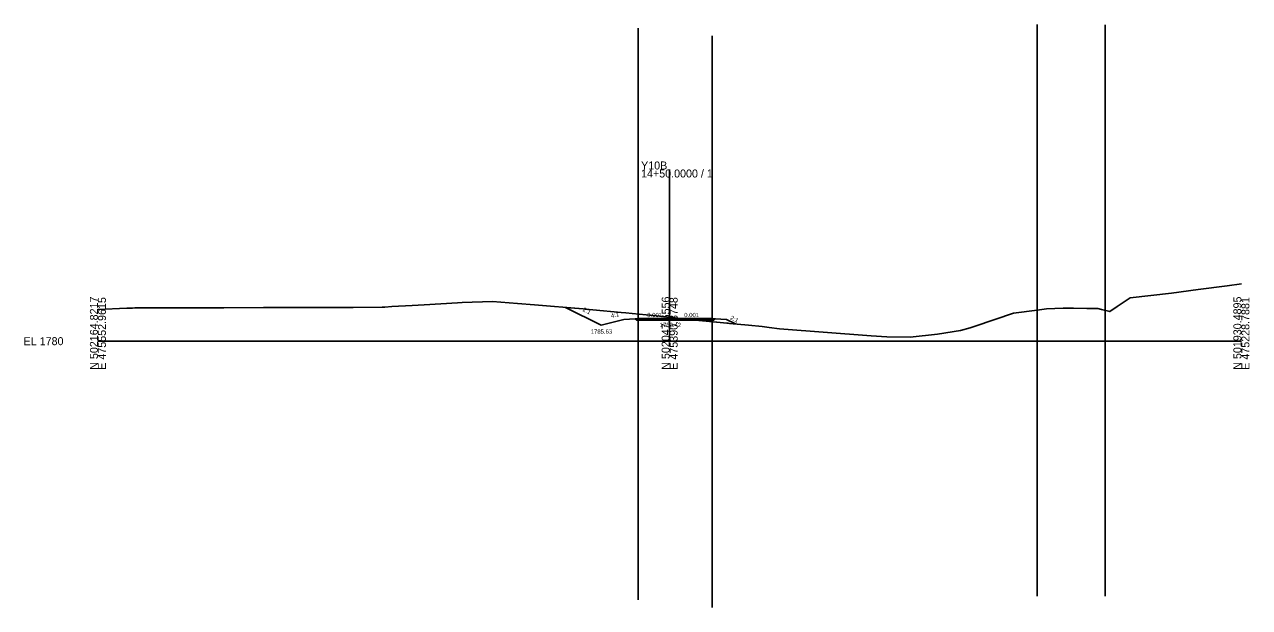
# Model space of a CAD drawing. Extents: x -26 to 1803, y -10 to 9558.
# Drawn here: x -25.7 to 402.8, y 4406.8 to 4610.8 of the extents above; entities that cross this region are included whole.
import ezdxf

# ---------------------------------------------------------------- set-up
doc = ezdxf.new("R2010")
doc.units = 0
for name, color, linetype in [('Exist Cross Section Cell', 7, 'Continuous'), ('Exist XS Center Line Elevation Label', 7, 'Continuous'), ('Exist XS Ground Line', 7, 'Continuous'), ('Prop XS Ditch Slope Text', 7, 'Continuous'), ('Prop XS Ditch Standard Text', 7, 'Continuous'), ('Prop XS Dump Level', 7, 'Continuous'), ('Prop XS Earthwork Shape', 7, 'Continuous'), ('Prop XS EOT Tick Mark', 7, 'Continuous'), ('Prop XS Finish Grade', 7, 'Continuous'), ('Prop XS Finish Grade Earthwork', 7, 'Continuous'), ('Prop XS Finish Grade Pavement', 7, 'Continuous'), ('Prop XS Hydro Typical Ditch Data', 7, 'Continuous'), ('Prop XS Pvmt Edge Slope', 7, 'Continuous'), ('Prop XS SE Text', 7, 'Continuous'), ('Prop XS Shoulder Borrow Shape', 7, 'Continuous'), ('Prop XS Side Slope Text', 7, 'Continuous'), ('Prop XS Subgrade Earthwork', 7, 'Continuous'), ('Scratch_Level_2', 7, 'Continuous')]:
    doc.layers.add(name, color=color, linetype=linetype)

msp = doc.modelspace()

# ---------------------------------------------------------------- linework, layer by layer
at = {"layer": 'Exist Cross Section Cell'}
for p, q in [((200, 4500), (200, 4560.08)), ((0, 4500), (200, 4500)), ((200, 4500), (400, 4500))]:
    msp.add_line(p, q, dxfattribs=at)
at = {"layer": 'Exist XS Ground Line'}
msp.add_lwpolyline([(0, 4511.14), (10.11, 4511.51), (12.07, 4511.59), (12.96, 4511.64), (13.97, 4511.69), (28.3, 4511.71), (30.98, 4511.72), (44.04, 4511.7), (57.97, 4511.76), (60.73, 4511.82), (75.68, 4511.8), (76.03, 4511.8), (83.09, 4511.82), (89.26, 4511.83), (99.44, 4511.91), (100.32, 4511.92), (102.83, 4512.12), (109.93, 4512.46), (114.09, 4512.75), (125.78, 4513.41), (127.45, 4513.54), (138.01, 4513.83), (146.74, 4513.17), (152.68, 4512.7), (158.34, 4512.29), (169.75, 4511.29), (170.68, 4511.19), (173.11, 4510.96), (183.03, 4510.05), (184.62, 4509.9), (186.83, 4509.7), (191.78, 4509.24), (195.37, 4508.89), (198.95, 4508.55), (200, 4508.42), (203.9, 4507.94), (207.71, 4507.5), (217.64, 4506.53), (220.05, 4506.29), (220.44, 4506.26), (220.97, 4506.21), (227.6, 4505.61), (232.39, 4505.1), (234.76, 4504.82), (238.43, 4504.33), (270.49, 4501.88), (275.97, 4501.51), (284.12, 4501.39), (293.66, 4502.51), (301.73, 4503.78), (305.18, 4504.67), (306.87, 4505.24), (320.31, 4509.82), (328.54, 4510.82), (331.86, 4511.36), (337.61, 4511.51), (341.27, 4511.59), (345.96, 4511.48), (349.82, 4511.41), (351.1, 4511.09), (353.98, 4510.33), (356.49, 4512.14), (361.08, 4515.14), (375.53, 4516.79), (384.91, 4518.14), (394.98, 4519.32), (400, 4520.03)], dxfattribs=at)
at = {"layer": 'Prop XS Dump Level'}
for p, q in [((189, 4507.93), (200, 4507.92)), ((200, 4507.92), (214.9, 4507.9))]:
    msp.add_line(p, q, dxfattribs=at)
at = {"layer": 'Prop XS Earthwork Shape'}
for points in [[(176, 4505.63), (163.61, 4511.83), (169.75, 4511.29), (170.68, 4511.19), (173.11, 4510.96), (183.03, 4510.05), (184.62, 4509.9), (186.83, 4509.7), (191.78, 4509.24), (195.37, 4508.89), (198.95, 4508.55), (200, 4508.42), (203.9, 4507.94), (207.71, 4507.5), (209.11, 4507.37), (200, 4507.37), (189, 4507.39), (188.46, 4507.39), (187.98, 4507.87), (184, 4507.63)], [(223.06, 4506.02), (219.9, 4507.6), (215.92, 4507.84), (215.44, 4507.36), (214.9, 4507.36), (209.11, 4507.37), (217.64, 4506.53), (220.05, 4506.29), (220.44, 4506.26), (220.97, 4506.21)]]:
    msp.add_lwpolyline(points, close=True, dxfattribs=at)
at = {"layer": 'Prop XS EOT Tick Mark'}
for p, q in [((189, 4507.93), (189, 4508.93)), ((214.9, 4507.9), (214.9, 4508.9))]:
    msp.add_line(p, q, dxfattribs=at)
at = {"layer": 'Prop XS Finish Grade'}
for p, q in [((189, 4507.93), (187.98, 4507.87)), ((214.9, 4507.9), (215.92, 4507.84))]:
    msp.add_line(p, q, dxfattribs=at)
at = {"layer": 'Prop XS Finish Grade Earthwork'}
for p, q in [((176, 4505.63), (163.61, 4511.83)), ((184, 4507.63), (176, 4505.63)), ((187.98, 4507.87), (184, 4507.63)), ((215.92, 4507.84), (219.9, 4507.6)), ((223.06, 4506.02), (219.9, 4507.6))]:
    msp.add_line(p, q, dxfattribs=at)
at = {"layer": 'Prop XS Finish Grade Pavement'}
for p, q in [((189, 4507.93), (200, 4507.92)), ((200, 4507.92), (214.9, 4507.9))]:
    msp.add_line(p, q, dxfattribs=at)
at = {"layer": 'Prop XS Hydro Typical Ditch Data'}
for p, q in [((176, 4505.63), (163.61, 4511.83)), ((184, 4507.63), (176, 4505.63)), ((223.06, 4506.02), (219.9, 4507.6))]:
    msp.add_line(p, q, dxfattribs=at)
at = {"layer": 'Prop XS Pvmt Edge Slope'}
for p, q in [((189, 4507.93), (188.46, 4507.39)), ((214.9, 4507.9), (215.44, 4507.36))]:
    msp.add_line(p, q, dxfattribs=at)
at = {"layer": 'Prop XS Shoulder Borrow Shape'}
for points in [[(189, 4507.93), (187.98, 4507.87), (188.46, 4507.39)], [(214.9, 4507.9), (215.44, 4507.36), (215.92, 4507.84)]]:
    msp.add_lwpolyline(points, close=True, dxfattribs=at)
at = {"layer": 'Prop XS Subgrade Earthwork'}
for p, q in [((188.46, 4507.39), (187.98, 4507.87)), ((189, 4507.39), (188.46, 4507.39)), ((200, 4507.37), (189, 4507.39)), ((214.9, 4507.36), (200, 4507.37)), ((214.9, 4507.36), (215.44, 4507.36)), ((215.44, 4507.36), (215.92, 4507.84))]:
    msp.add_line(p, q, dxfattribs=at)
at = {"layer": 'Scratch_Level_2'}
for p, q in [((189, 4609.5), (189, 4409.5)), ((214.9, 4606.8), (214.9, 4406.8)), ((328.54, 4610.82), (328.54, 4410.82)), ((352.38, 4610.75), (352.38, 4410.75))]:
    msp.add_line(p, q, dxfattribs=at)

# ---------------------------------------------------------------- texts
at = {"layer": 'Exist Cross Section Cell'}
for s, p in [('Y10B', (190, 4560.08)), ('14+50.0000 / 1', (190, 4557.28)), ('EL 1780', (-26, 4498.6))]:
    msp.add_text(s, height=2.8, dxfattribs=at).set_placement(p)
for s, p in [('N 502164.8217', (0, 4490)), ('E 475552.9615', (2.8, 4490)), ('N 502047.6556', (200, 4490)), ('E 475390.8748', (202.8, 4490)), ('N 501930.4895', (400, 4490)), ('E 475228.7881', (402.8, 4490))]:
    msp.add_text(s, height=2.8, rotation=90, dxfattribs=at).set_placement(p)
at = {"layer": 'Exist XS Center Line Elevation Label'}
msp.add_text('1788.42', height=1.5, dxfattribs=at).set_placement((196.51, 4504.92))
at = {"layer": 'Prop XS Ditch Slope Text'}
msp.add_text('4:1', height=1.5, rotation=14.0362, dxfattribs=at).set_placement((179.64, 4508.09))
at = {"layer": 'Prop XS Ditch Standard Text'}
msp.add_text('1785.63', height=1.5, dxfattribs=at).set_placement((172.4, 4502.63))
at = {"layer": 'Prop XS Dump Level'}
for p in [(184, 4507.59), (219.9, 4507.56)]:
    msp.add_text('Case1', height=0.04, dxfattribs=at).set_placement(p)
at = {"layer": 'Prop XS SE Text'}
for p in [(192.15, 4508.42), (205.1, 4508.41)]:
    msp.add_text('0.001', height=1.5, rotation=359.9427, dxfattribs=at).set_placement(p)
at = {"layer": 'Prop XS Side Slope Text'}
for p in [(169.41, 4510.6), (221.03, 4507.72)]:
    msp.add_text('2:1', height=1.5, rotation=333.4349, dxfattribs=at).set_placement(p)

doc.saveas('drawing.dxf')
